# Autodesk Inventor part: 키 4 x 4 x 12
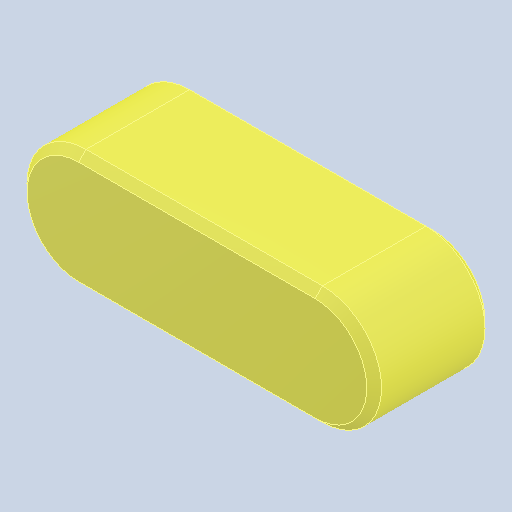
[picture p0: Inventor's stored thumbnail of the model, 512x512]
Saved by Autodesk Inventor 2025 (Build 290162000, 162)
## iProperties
Created: 2025-08
Part Number: 키 4 x 4 x 12
Material: 강철, 연강
Description: 키 및 해당 키홈
Document SubType Name: Modeling
Designer: infra028
Density: 7.85 g/cm^3
Appearance: 기본값
Author: jhkim
Sending System: Autodesk Inventor 2026
Preprocessor: ST-DEVELOPER v20.1
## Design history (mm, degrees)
feature "Solid1"
node "솔리드1"
